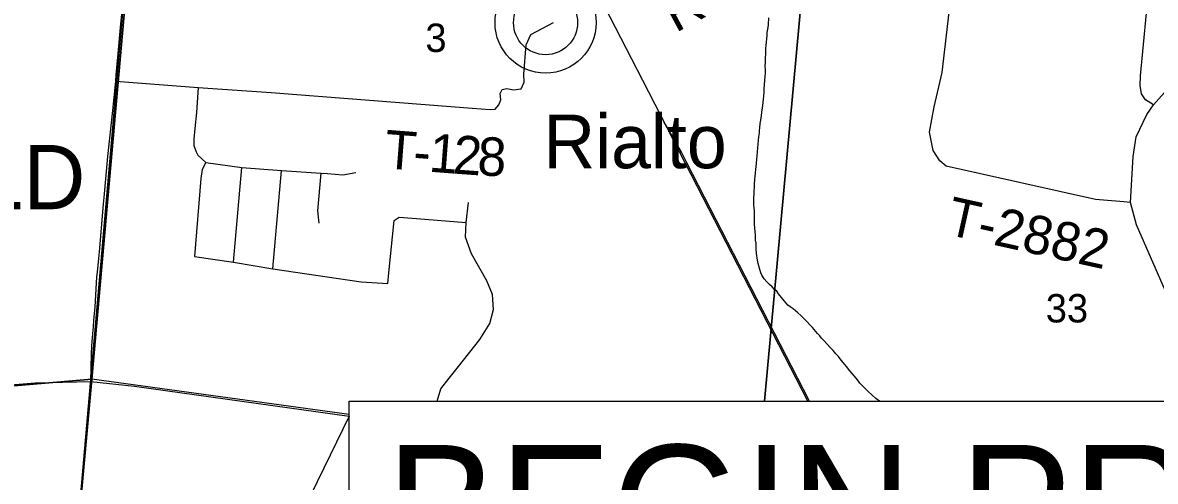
# Model space of a CAD drawing. Extents: x 0 to 34, y 0 to 22.
# Drawn here: x 4.396 to 6.065, y 16.296 to 16.973 of the extents above; entities that cross this region are included whole.
import ezdxf

# ---------------------------------------------------------------- set-up
doc = ezdxf.new("R2010")
doc.units = 0
for name, color, linetype in [('GM_X_Corporation_Text', 7, 'Continuous'), ('GM_X_County_Road', 7, 'Continuous'), ('GM_X_Minor_River', 7, 'Continuous'), ('GM_X_Rail_Line', 7, 'Continuous'), ('GM_X_Section', 7, 'Continuous'), ('GM_X_Section_Text', 7, 'Continuous'), ('GM_X_State_Route', 7, 'Continuous'), ('GM_X_Township_Road', 7, 'Continuous'), ('GM_X_Township_Road_Text', 7, 'Continuous'), ('GM_X_Unincorporated', 7, 'Continuous'), ('GM_X_Unincorporated_Location', 7, 'Continuous'), ('GM_X_Unincorporated_Text', 7, 'Continuous'), ('SH_Text', 7, 'Continuous')]:
    doc.layers.add(name, color=color, linetype=linetype)

msp = doc.modelspace()

# ---------------------------------------------------------------- linework, layer by layer
at = {"layer": 'GM_X_County_Road'}
for points in [[(3.7629, 16.3834), (3.7923, 16.3861), (3.8158, 16.3891), (3.8791, 16.3942), (3.9679, 16.4025), (4.1131, 16.4161), (4.1592, 16.4206), (4.4147, 16.4416), (4.4965, 16.4435)], [(4.4965, 16.4435), (4.5612, 16.4368), (4.8773, 16.3926)]]:
    msp.add_lwpolyline(points, dxfattribs=at)
at = {"layer": 'GM_X_Minor_River'}
for points in [[(5.4818, 16.8136), (5.4822, 16.8177), (5.4827, 16.8242), (5.4836, 16.8291), (5.4845, 16.836), (5.4853, 16.8409), (5.4862, 16.8473), (5.4871, 16.8545), (5.4876, 16.8599), (5.4881, 16.864), (5.4886, 16.8709), (5.4887, 16.8747), (5.4892, 16.8819), (5.4897, 16.8872), (5.4898, 16.8937), (5.4903, 16.8978), (5.4904, 16.9024), (5.4901, 16.9093), (5.4906, 16.9127), (5.491, 16.9347), (5.4915, 16.9397), (5.492, 16.9438), (5.4924, 16.9488), (5.4929, 16.9541), (5.493, 16.9579), (5.4943, 16.9655), (5.4948, 16.97), (5.4953, 16.9799)], [(5.6586, 16.4145), (5.653, 16.4186), (5.6474, 16.4233), (5.6411, 16.4291), (5.6352, 16.435), (5.6296, 16.4412), (5.6259, 16.4462), (5.6215, 16.4512), (5.6182, 16.4555), (5.6149, 16.4594), (5.6097, 16.4659), (5.6049, 16.4717), (5.602, 16.4752), (5.5979, 16.4802), (5.5942, 16.4845), (5.5901, 16.4892), (5.5864, 16.4934), (5.5765, 16.5039), (5.5731, 16.5074), (5.5705, 16.5109), (5.5672, 16.5144), (5.5595, 16.5233), (5.548, 16.5353), (5.5424, 16.5407), (5.538, 16.545), (5.5313, 16.5505), (5.5268, 16.5536), (5.5234, 16.5563), (5.5183, 16.5622), (5.5138, 16.5676), (5.5098, 16.5726), (5.5072, 16.5765), (5.5039, 16.5792), (5.5002, 16.5831), (5.4965, 16.5866), (5.4924, 16.5905), (5.4883, 16.5951), (5.485, 16.6005), (5.4836, 16.604), (5.4822, 16.6089), (5.4797, 16.6173), (5.4787, 16.6223), (5.4773, 16.6322), (5.4767, 16.6387), (5.4768, 16.6437), (5.4765, 16.6475), (5.4758, 16.6517), (5.4756, 16.6593), (5.4747, 16.6696), (5.4741, 16.6757), (5.4743, 16.6878), (5.4741, 16.6958), (5.4738, 16.6993), (5.4731, 16.7042), (5.4733, 16.7145), (5.4738, 16.7209), (5.4739, 16.7251), (5.4744, 16.7289), (5.4745, 16.7342), (5.4746, 16.7422), (5.4751, 16.746), (5.4756, 16.7513), (5.4761, 16.7563), (5.477, 16.765), (5.4779, 16.7718), (5.4784, 16.7756), (5.4789, 16.7828), (5.4794, 16.7878), (5.4798, 16.7935), (5.4803, 16.7995), (5.4808, 16.8045), (5.4817, 16.8102), (5.4818, 16.8136)]]:
    msp.add_lwpolyline(points, dxfattribs=at)
at = {"layer": 'GM_X_Rail_Line'}
for points in [[(5.5527, 16.4145), (5.3725, 16.7649), (5.3098, 16.8872), (5.1812, 17.1373), (5.0499, 17.393), (5.037, 17.4166), (5.0252, 17.437), (5.0139, 17.4546), (5.001, 17.4731), (4.9895, 17.4883), (4.9752, 17.5053), (4.9605, 17.5218), (4.9371, 17.5451), (4.921, 17.5598), (4.9044, 17.5741), (4.8871, 17.5886), (4.8723, 17.5997), (4.7884, 17.6623), (4.6417, 17.7708), (4.3528, 17.9844), (3.8782, 18.3346)], [(5.5555, 16.4145), (5.3747, 16.766), (5.3668, 16.7815), (5.3411, 16.8261)]]:
    msp.add_lwpolyline(points, dxfattribs=at)
at = {"layer": 'GM_X_Section'}
for points in [[(3.5572, 17.3639), (4.5906, 17.4897), (4.4981, 16.447), (3.4704, 16.3589)], [(4.4981, 16.447), (4.4056, 15.4266), (3.385, 15.3645), (3.4704, 16.3589)]]:
    msp.add_lwpolyline(points, close=True, dxfattribs=at)
for points in [[(4.8773, 16.3947), (4.4981, 16.447), (4.5906, 17.4897), (5.5736, 17.336), (5.489, 16.4145)], [(5.489, 16.4145), (5.5736, 17.336), (6.585, 17.1294), (6.5225, 16.4145)]]:
    msp.add_lwpolyline(points, dxfattribs=at)
at = {"layer": 'GM_X_State_Route'}
for p, q in [((4.5064, 16.6049), (4.5085, 16.6249)), ((4.5005, 16.5242), (4.5013, 16.5342)), ((4.4996, 16.5142), (4.5005, 16.5242))]:
    msp.add_line(p, q, dxfattribs=at)
for points in [[(4.5342, 16.8956), (4.5364, 16.9219), (4.5409, 16.9707), (4.5426, 16.9849), (4.543, 16.9897)], [(4.5164, 16.715), (4.5219, 16.7753), (4.529, 16.8433), (4.5335, 16.8862), (4.5342, 16.8956)], [(4.5085, 16.6249), (4.5095, 16.6348), (4.5154, 16.7049), (4.5164, 16.715)], [(4.5013, 16.5342), (4.503, 16.5532), (4.5057, 16.5979), (4.5064, 16.6049)], [(4.4976, 16.484), (4.498, 16.4962), (4.4996, 16.5142)], [(4.4647, 16.0728), (4.4668, 16.0966), (4.4691, 16.1236), (4.4735, 16.1758), (4.4747, 16.1897), (4.4805, 16.2543), (4.4867, 16.3271), (4.4929, 16.4025), (4.4965, 16.4435), (4.4976, 16.484)]]:
    msp.add_lwpolyline(points, dxfattribs=at)
at = {"layer": 'GM_X_Township_Road'}
for p, q in [((4.707, 16.6196), (4.719, 16.7593)), ((4.7649, 16.6096), (4.7778, 16.7546)), ((6.0184, 16.7085), (5.9884, 16.7109)), ((6.0283, 16.7077), (6.0184, 16.7085))]:
    msp.add_line(p, q, dxfattribs=at)
for points in [[(5.9884, 16.7109), (5.9765, 16.7119), (5.7564, 16.761), (5.7473, 16.7687), (5.7375, 16.7841), (5.7319, 16.8114), (5.7389, 16.8486), (5.7508, 16.8991), (5.7676, 17.0435), (5.7764, 17.1627), (5.7906, 17.2278)], [(6.062, 16.8517), (6.0504, 16.8591), (6.0441, 16.8679), (6.0424, 16.8798), (6.0427, 16.8942), (6.0518, 16.9867), (6.0466, 16.9877)], [(4.5335, 16.8862), (4.6547, 16.8768), (4.7622, 16.8695), (5.0586, 16.8468), (5.0851, 16.8444), (5.0924, 16.8449), (5.0979, 16.8513), (5.1007, 16.8591), (5.0997, 16.8683), (5.1025, 16.8743), (5.1097, 16.8757), (5.1191, 16.8735), (5.1307, 16.8749), (5.1349, 16.8851), (5.1343, 16.8969), (5.1379, 16.94), (5.1449, 16.955), (5.1782, 16.9728)], [(4.6547, 16.8768), (4.6526, 16.8404), (4.6501, 16.8167), (4.6485, 16.801), (4.6484, 16.7915), (4.6518, 16.7823), (4.6545, 16.7774), (4.6659, 16.7663), (4.719, 16.7593), (4.7778, 16.7546), (4.8361, 16.7508), (4.8452, 16.7501), (4.8681, 16.7485), (4.8873, 16.7518)], [(6.152, 16.4145), (6.1382, 16.4459), (6.0935, 16.5454), (6.0368, 16.6744), (6.0283, 16.7077), (6.0319, 16.7753), (6.0364, 16.8044), (6.0522, 16.837), (6.062, 16.8517), (6.0862, 16.8783)], [(4.6659, 16.7663), (4.6609, 16.7561), (4.6587, 16.7431), (4.6496, 16.6279), (4.707, 16.6196), (4.7649, 16.6096), (4.8948, 16.5904), (4.9343, 16.5879), (4.9359, 16.6039), (4.9434, 16.6809), (4.951, 16.686), (4.9765, 16.684), (5.0495, 16.6782)], [(4.8331, 16.6769), (4.8309, 16.6954), (4.8361, 16.7508)], [(5.0383, 16.4656), (5.0699, 16.5054), (5.0842, 16.5289), (5.0898, 16.5499), (5.0884, 16.572), (5.08, 16.592), (5.0576, 16.6316), (5.0488, 16.6565), (5.0495, 16.6782), (5.053, 16.7077)], [(5.0068, 16.4145), (5.0124, 16.4328), (5.0245, 16.4483), (5.0383, 16.4656)]]:
    msp.add_lwpolyline(points, dxfattribs=at)
at = {"layer": 'GM_X_Unincorporated'}
for radius in [0.0744, 0.0472]:
    msp.add_circle((5.1665, 16.9726), radius, dxfattribs=at)
at = {"layer": 'GM_X_Unincorporated_Location'}
msp.add_line((5.1665, 16.9726), (5.1665, 16.9726), dxfattribs=at)
at = {"layer": 'SH_Text'}
msp.add_lwpolyline([(4.4077, 15.4283), (4.5869, 17.4825), (4.6405, 17.7714), (4.6732, 18.1415), (4.69, 18.3364), (4.6901, 18.5827)], dxfattribs=at)
for points in [[(4.8773, 16.4145), (7.1778, 16.4145), (7.1778, 15.8198), (4.8773, 15.8198)], [(4.8773, 16.3926), (4.4077, 15.4283), (4.8773, 15.8198)]]:
    msp.add_lwpolyline(points, close=True, dxfattribs=at)

# ---------------------------------------------------------------- texts
at = {"layer": 'GM_X_Corporation_Text'}
msp.add_text('FAIRFIELD', height=0.0947, rotation=0, dxfattribs=at).set_placement((3.8414, 16.6976))
at = {"layer": 'GM_X_Section_Text'}
for s, height, p in [('3', 0.0419, (4.9895, 16.9294)), ('33', 0.04186, (5.9033, 16.5306))]:
    msp.add_text(s, height=height, rotation=0, dxfattribs=at).set_placement(p)
at = {"layer": 'GM_X_Township_Road_Text'}
for s, height, rotation, p in [('RD', 0.05682, 28.3345, (5.358, 16.9571)), ('T', 0.0568, 355.5492, (4.9278, 16.7581)), ('1', 0.0568, 355.6388, (4.9935, 16.753)), ('2', 0.0568, 355.915, (5.0287, 16.7503)), ('8', 0.0568, 357.3997, (5.0653, 16.7477)), ('-', 0.0568, 355.5666, (4.9702, 16.7548)), ('T-2882', 0.05682, 347.4967, (5.7544, 16.661))]:
    msp.add_text(s, height=height, rotation=rotation, dxfattribs=at).set_placement(p)
at = {"layer": 'GM_X_Unincorporated_Text'}
msp.add_text('Rialto', height=0.07898, rotation=0, dxfattribs=at).set_placement((5.1633, 16.758))
at = {"layer": 'SH_Text'}
msp.add_text('BEGIN PROJECT', height=0.18634, dxfattribs=at).set_placement((4.9313, 16.1636))

doc.saveas('drawing.dxf')
